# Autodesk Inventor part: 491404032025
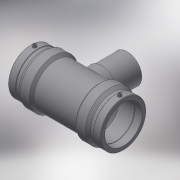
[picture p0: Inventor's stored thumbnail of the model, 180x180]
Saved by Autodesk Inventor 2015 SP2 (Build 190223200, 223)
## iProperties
Created: 2017-06
Part Number: 491404032025
Material: Generic
Description: PLASSON REDUCING TEE 32x25x32
Document SubType Name: Modeling
Designer: KIM
Mass: 83.9407 g
Surface Area: 353.978 cm^2
Volume: 83.9407 cm^3
Density: 1 g/cm^3
Appearance: Default
Author: KIM
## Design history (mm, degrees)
derived "491404.ipt"
feature "Solid1::491404.ipt"
tag "TaggingFeature1"
body "Solid1"
other parameters: "d0" = 104, "d1" = 32, "d2" = 44, "d3" = 39, "d4" = 20.8, "d5" = 39.6, "d6" = 30.4, "d7" = 32, "d8" = 168 deg, "d10" = 15.6, "d11" = 5.2, "d13" = 104, "d14" = 17.6296, "d17" = 28.8, "d18" = 32, "d19" = 3.52592, "d20" = 168 deg, "d22" = 40.92, "d23" = 44, "d25" = 135 deg, "d26" = 72.8, "d29" = 43, "d30" = 15, "d31" = 41.6, "d34" = 5 deg, "d35" = 15, "d39" = 5 deg, "d41" = 4, "d42" = 14, "d43" = 0, "d45" = 4, "d46" = 6, "d47" = 0, "d48" = -66, "d49" = 25, "d51" = 0, "d54" = 0, "d55" = 39.6, "d56" = 44, "d57" = 36.4, "d58" = 135 deg, "d59" = 39, "d60" = 39, "d61" = 135 deg, "d62" = 66, "d72" = 47.32, "d73" = 23.66, "d74" = -66, "d75" = 26.25, "d77" = 0, "d80" = 0, "d81" = 25, "d82" = 44, "d83" = 0, "d84" = 3, "d85" = 0, "d86" = 13, "d87" = 40.1016, "d88" = 5.2, "d89" = 3, "d90" = 0, "d_" = 32, "L_" = 104, "L_1" = 39, "D_" = 44, "A_" = 43, "d_2" = 12, "H_" = 66, "d_1" = 25
